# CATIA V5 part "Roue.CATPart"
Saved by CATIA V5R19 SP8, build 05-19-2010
Part number: Roue
Bounding box of the stored display mesh (mm): x -65.5 to -15.5, y -55.827 to 55.827, z -56 to 56
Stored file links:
  G:\EU_thinkMotion\CFAO_2010\MMS_groupe3\MMS_groupe3\jbonnamy\jbonnamy_cfao\Roue.CATPart
  G:\EU_thinkMotion\CFAO_2010\MMS_groupe3\MMS_groupe3\jbonnamy\jbonnamy_cfao\jbonnamy_suspension.arriere.directionnelle.CATProduct
  G:\EU_thinkMotion\CFAO_2010\MMS_groupe3\MMS_groupe3\jbonnamy\jbonnamy_cfao\Moyeu.CATPart
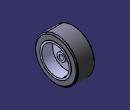
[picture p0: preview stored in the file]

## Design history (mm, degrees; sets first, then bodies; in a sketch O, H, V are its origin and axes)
External parameters (linked from other documents)
  External.Diametre.moyeu = 12 mm
  External.Longueur.moyeu = 40 mm
Set1
  DatumCurve1: linked copy from another document
  Plane1 "Plan.moyeu": linked copy from another document
Body1 "jante" (main body)
  Sketch1 on zx-plane, origin (0, 0, 0), H (-1, 0, 0), V (0, 0, 1)
    line L1 (30.5, 6) -> (60.5, 6)
    line L2 (60.5, 6) -> (60.5, 11)
    line L3 (60.5, 11) -> (50.5, 11)
    line L4 (30.5, 6) -> (30.5, 11)
    line L5 (30.5, 11) -> (40.3966, 11)
    line L6 (65.5, 36) -> (65.5, 41)
    line L7 (65.5, 41) -> (15.5, 41)
    line L8 (15.5, 41) -> (15.5, 36)
    reference intersected line E1 through (20.5, 0) direction (0, -1) from Plane1
    line L9 (65.5, 36) -> (54.1052, 36)
    line L10 (54.1052, 36) -> (50.5, 11)
    line L11 (40.3966, 11) -> (44.0017, 36)
    line L12 (44.0017, 36) -> (15.5, 36)
    distance L1 H = 6 {= External.Diametre.moyeu /2}
    distance L4 L2 = 30
    distance L6 L8 = 50
    distance L2 E1 = 40 {= External.Longueur.moyeu}
    length L3 = 10
    distance L3 L1 = 5
    distance L3 L5 = 0
    distance L7 L1 = 35
    distance L12 L9 = 0
    distance L12 L7 = 5
    distance L10 L11 = 10
    distance L6 L2 = 5
  Shaft1: profile Sketch1, axis edge of DatumCurve1, angle 360
Body2 "Pneu"
  Sketch2 on zx-plane, origin (0, 0, 0), H (-1, 0, 0), V (0, 0, 1)
    line L1 (64.5, 41) -> (16.5, 41)
    line L2 (64.5, 41) -> (64.5, 53)
    line L3 (61.5, 56) -> (19.5, 56)
    line L4 (16.5, 53) -> (16.5, 41)
    reference intersected line E1 through (20.5, 0) direction (0, -1) from Plane1
    arc A1 centre (61.5, 53) radius 3 from (64.5, 53) to (61.5, 56) ccw
    point P5 (61.5, 53)
    arc A2 centre (19.5, 53) radius 3 from (19.5, 56) to (16.5, 53) ccw
    point P8 (19.5, 53)
    distance L1 H = 41 {= 35mm+External.Diametre.moyeu /2}
    distance L1 L3 = 15
    distance L2 L4 = 48
    distance L2 E1 = 44 {= External.Longueur.moyeu +4mm}
    radius A1 = 3
    radius A2 = 3
    distance P8 L3 = 3
    distance L3 P5 = 3
    distance P5 L2 = 3
    distance P8 L4 = 3
  Shaft2: profile Sketch2, axis axis of face of Shaft1 from Sketch1.L7, angle 360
